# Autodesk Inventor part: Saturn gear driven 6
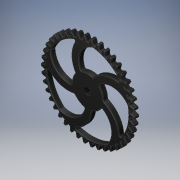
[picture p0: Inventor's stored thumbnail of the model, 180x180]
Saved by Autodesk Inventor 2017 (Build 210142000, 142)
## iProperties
Created: 2016-06
Part Number: Saturn gear driven 6
Material: Generic
Document SubType Name: Modeling
Designer: Stan
Density: 1 g/cm^3
Appearance: Glossy - Black
Author: Stan
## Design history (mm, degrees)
sketch "Sketch1"
  geometry: A1 r 22.686 centre (29.022, -41.77) between (8.865, -52.178) and (11.795, -56.53); A2 r 22.686 centre (29.022, -41.77) between (8.865, -52.178) and (11.795, -56.53); A3 r 22.686 centre (-15.421, -48.469) between (5.391, -57.495) and (6.908, -52.473); A4 r 22.686 centre (-15.421, -48.469) between (5.391, -57.495) and (6.908, -52.473); A5 r 22.686 centre (34.924, -36.978) between (16.543, -50.274) and (20.089, -54.14); A6 r 22.686 centre (34.924, -36.978) between (16.543, -50.274) and (20.089, -54.14); A7 r 22.686 centre (-8.025, -50.226) between (13.9, -56.049) and (14.652, -50.857); A8 r 22.686 centre (-8.025, -50.226) between (13.9, -56.049) and (14.652, -50.857); A9 r 22.686 centre (40.045, -31.36) between (23.851, -47.247) and (27.933, -50.542); A10 r 22.686 centre (40.045, -31.36) between (23.851, -47.247) and (27.933, -50.542); A11 r 22.686 centre (-0.45, -50.861) between (22.099, -53.351) and (22.068, -48.106); A12 r 22.686 centre (-0.45, -50.861) between (22.099, -53.351) and (22.068, -48.106); A13 r 22.686 centre (44.272, -25.041) between (30.627, -43.164) and (35.154, -45.814); A14 r 22.686 centre (44.272, -25.041) between (30.627, -43.164) and (35.154, -45.814); A15 r 22.686 centre (7.136, -50.36) between (29.804, -49.462) and (28.991, -44.279); A16 r 22.686 centre (7.136, -50.36) between (29.804, -49.462) and (28.991, -44.279); A17 r 22.686 centre (47.509, -18.163) between (36.718, -38.118) and (41.59, -40.063); A18 r 22.686 centre (47.509, -18.163) between (36.718, -38.118) and (41.59, -40.063); A19 r 22.686 centre (14.562, -48.734) between (36.843, -44.467) and (35.267, -39.464); A20 r 22.686 centre (14.562, -48.734) between (36.843, -44.467) and (35.267, -39.464); A21 r 22.686 centre (49.686, -10.879) between (41.989, -32.219) and (47.096, -33.417); A22 r 22.686 centre (49.686, -10.879) between (41.989, -32.219) and (47.096, -33.417); A23 r 22.686 centre (21.663, -46.019) between (43.059, -38.48) and (40.755, -33.767); A24 r 22.686 centre (21.663, -46.019) between (43.059, -38.48) and (40.755, -33.767); A25 r 22.686 centre (50.752, -3.353) between (46.322, -25.601) and (51.551, -26.024); A26 r 22.686 centre (50.752, -3.353) between (46.322, -25.601) and (51.551, -26.024); A27 r 22.686 centre (28.28, -42.277) between (48.313, -31.632) and (45.332, -27.315); A28 r 22.686 centre (28.28, -42.277) between (48.313, -31.632) and (45.332, -27.315); A29 r 22.686 centre (50.685, 4.249) between (49.62, -18.411) and (54.854, -18.05); A30 r 22.686 centre (50.685, 4.249) between (49.62, -18.411) and (54.854, -18.05); A31 r 22.686 centre (34.265, -37.59) between (52.488, -24.078) and (48.897, -20.254); A32 r 22.686 centre (34.265, -37.59) between (52.488, -24.078) and (48.897, -20.254); A33 r 22.686 centre (49.486, 11.756) between (51.81, -10.81) and (56.931, -9.673); A34 r 22.686 centre (49.486, 11.756) between (51.81, -10.81) and (56.931, -9.673); A35 r 22.686 centre (39.484, -32.063) between (55.49, -15.986) and (51.37, -12.74); A36 r 22.686 centre (39.484, -32.063) between (55.49, -15.986) and (51.37, -12.74); A37 r 22.686 centre (47.181, 19) between (52.843, -2.968) and (57.737, -1.08); A38 r 22.686 centre (47.181, 19) between (52.843, -2.968) and (57.737, -1.08); A39 r 22.686 centre (43.822, -25.82) between (57.253, -7.538) and (52.695, -4.941); A40 r 22.686 centre (43.822, -25.82) between (57.253, -7.538) and (52.695, -4.941); A41 r 22.686 centre (43.822, 25.82) between (52.695, 4.941) and (57.253, 7.538); A42 r 22.686 centre (43.822, 25.82) between (52.695, 4.941) and (57.253, 7.538); A43 r 22.686 centre (47.181, -19) between (57.737, 1.08) and (52.843, 2.968); A44 r 22.686 centre (47.181, -19) between (57.737, 1.08) and (52.843, 2.968); A45 r 22.686 centre (39.484, 32.063) between (51.37, 12.74) and (55.49, 15.986); A46 r 22.686 centre (39.484, 32.063) between (51.37, 12.74) and (55.49, 15.986); A47 r 22.686 centre (49.486, -11.756) between (56.931, 9.673) and (51.81, 10.81); A48 r 22.686 centre (49.486, -11.756) between (56.931, 9.673) and (51.81, 10.81); A49 r 22.686 centre (34.265, 37.59) between (48.897, 20.254) and (52.488, 24.078); A50 r 22.686 centre (34.265, 37.59) between (48.897, 20.254) and (52.488, 24.078); A51 r 22.686 centre (50.685, -4.249) between (54.854, 18.05) and (49.62, 18.411); A52 r 22.686 centre (50.685, -4.249) between (54.854, 18.05) and (49.62, 18.411); A53 r 22.686 centre (28.28, 42.277) between (45.332, 27.315) and (48.313, 31.632); A54 r 22.686 centre (28.28, 42.277) between (45.332, 27.315) and (48.313, 31.632); A55 r 22.686 centre (50.752, 3.353) between (51.551, 26.024) and (46.322, 25.601); A56 r 22.686 centre (50.752, 3.353) between (51.551, 26.024) and (46.322, 25.601); A57 r 22.686 centre (21.663, 46.019) between (40.755, 33.767) and (43.059, 38.48); A58 r 22.686 centre (21.663, 46.019) between (40.755, 33.767) and (43.059, 38.48); A59 r 22.686 centre (49.686, 10.879) between (47.096, 33.417) and (41.989, 32.219); A60 r 22.686 centre (49.686, 10.879) between (47.096, 33.417) and (41.989, 32.219); A61 r 22.686 centre (14.562, 48.734) between (35.267, 39.464) and (36.843, 44.467); A62 r 22.686 centre (14.562, 48.734) between (35.267, 39.464) and (36.843, 44.467); A63 r 22.686 centre (47.509, 18.163) between (41.59, 40.063) and (36.718, 38.118); A64 r 22.686 centre (47.509, 18.163) between (41.59, 40.063) and (36.718, 38.118)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; 1 further point
  constraints: 732 point on circle, 366 centre point, 8 horizontal alignment, 8 vertical alignment, 1022 other
extrude "Extrusion1" new body sketch "Sketch1" distance "d0" = 6.35; taper "d1" = 0 deg
fillet "Fillet1" dims "d9" = 0.79375
fillet "Fillet3" dims "d11" = 0.79375
fillet "Fillet4" dims "d12" = 0.79375
fillet "Fillet6" dims "d14" = 0.79375
fillet "Fillet7" dims "d15" = 0.79375
fillet "Fillet8" dims "d16" = 0.79375
body "Solid1"
other parameters: "d17" = 8.73125
